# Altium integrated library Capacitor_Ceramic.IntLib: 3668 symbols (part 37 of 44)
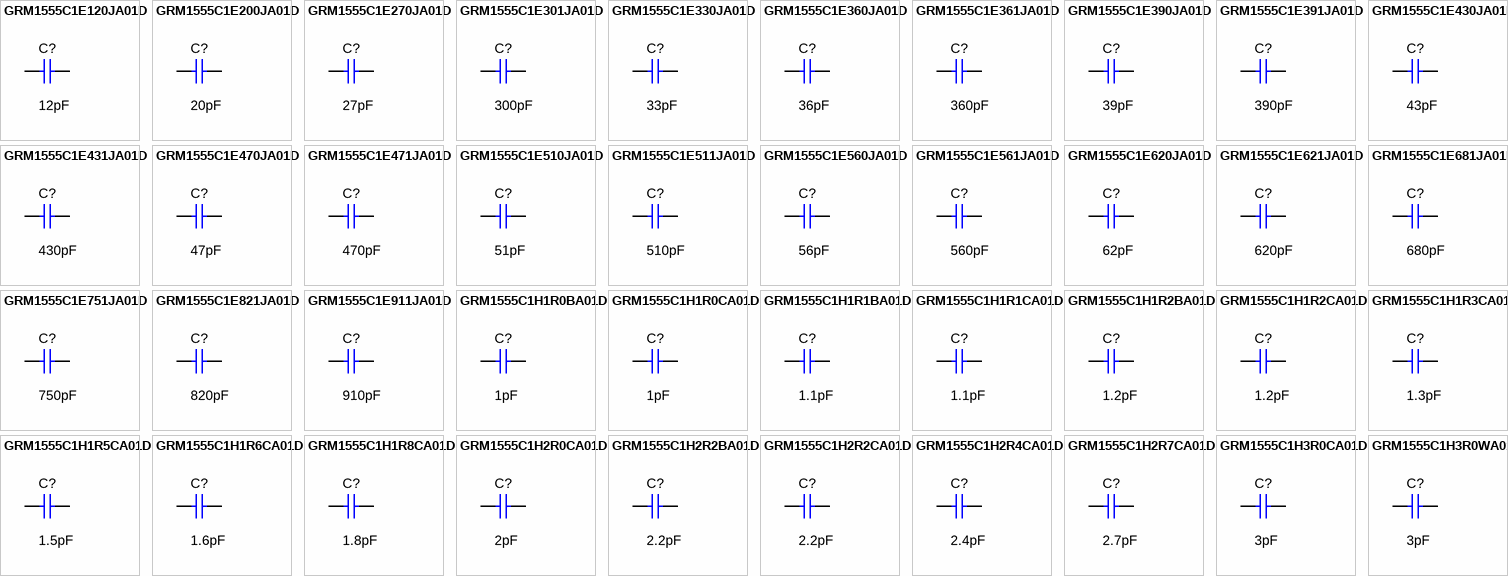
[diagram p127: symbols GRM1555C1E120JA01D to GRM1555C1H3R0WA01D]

## GRM1555C1E911JA01D
designator C?  ValueDisplayed: 910pF  (hidden comment: GRM1555C1E911JA01D)
CAP, CERM, 910 pF, 25 V,+/- 5%, C0G/NP0, 0402; Manufacturer: MuRata; Polarized: N; CompType: Capacitor; Value: 910pF; U/M: EA; Cap_F: 0.00000000091; Tolerance_%: 5; VDC_V: 25; Value2: 25V; TaMin_C: -55; TaMax_C: 125; Cap_Case: 0402; SizeArea_mm2: 0.5; SizeAreaWB_mm2: 3; SizeX_mm: 1; SizeZ_mm: 0.6; AEC Category: Q200
signal-integrity model Cap
simulation model Cap
footprint 0402
footprint 0402M
footprint 0402L
footprint 0402S
pins: 1, 2

## GRM1555C1H1R0BA01D
designator C?  ValueDisplayed: 1pF  (hidden comment: GRM1555C1H1R0BA01D)
CAP, CERM, 1 pF, 50 V,+/- 10%, C0G/NP0, 0402; Manufacturer: MuRata; Polarized: N; CompType: Capacitor; Value: 1pF; U/M: EA; Cap_F: 0.000000000001; Tolerance_%: 10; VDC_V: 50; Value2: 50V; TaMin_C: -55; TaMax_C: 125; Cap_Case: 0402; SizeArea_mm2: 0.5; SizeAreaWB_mm2: 3; SizeX_mm: 1; SizeZ_mm: 0.6; AEC Category: Q200
signal-integrity model Cap
simulation model Cap
footprint 0402
footprint 0402M
footprint 0402L
footprint 0402S
pins: 1, 2

## GRM1555C1H1R0CA01D
designator C?  ValueDisplayed: 1pF  (hidden comment: GRM1555C1H1R0CA01D)
CAP, CERM, 1 pF, 50 V,+/- 5%, C0G/NP0, 0402; Manufacturer: MuRata; Polarized: N; CompType: Capacitor; Value: 1pF; U/M: EA; Cap_F: 0.000000000001; Tolerance_%: 5; VDC_V: 50; Value2: 50V; TaMin_C: -55; TaMax_C: 125; Cap_Case: 0402; SizeArea_mm2: 0.5; SizeAreaWB_mm2: 3; SizeX_mm: 1; SizeZ_mm: 0.6; AEC Category: Q200; Green_Lifecycle: Active; Green_REACh: Passed
signal-integrity model Cap
simulation model Cap
footprint 0402
footprint 0402M
footprint 0402L
footprint 0402S
pins: 1, 2

## GRM1555C1H1R1BA01D
designator C?  ValueDisplayed: 1.1pF  (hidden comment: GRM1555C1H1R1BA01D)
CAP, CERM, 1.1 pF, 50 V,+/- 10%, C0G/NP0, 0402; Manufacturer: MuRata; Polarized: N; CompType: Capacitor; Value: 1.1pF; U/M: EA; Cap_F: 0.0000000000011; Tolerance_%: 10; VDC_V: 50; Value2: 50V; TaMin_C: -55; TaMax_C: 125; Cap_Case: 0402; SizeArea_mm2: 0.5; SizeAreaWB_mm2: 3; SizeX_mm: 1; SizeZ_mm: 0.6; AEC Category: Q200
signal-integrity model Cap
simulation model Cap
footprint 0402
footprint 0402M
footprint 0402L
footprint 0402S
pins: 1, 2

## GRM1555C1H1R1CA01D
designator C?  ValueDisplayed: 1.1pF  (hidden comment: GRM1555C1H1R1CA01D)
CAP, CERM, 1.1 pF, 50 V,+/- 5%, C0G/NP0, 0402; Manufacturer: MuRata; Polarized: N; CompType: Capacitor; Value: 1.1pF; U/M: EA; Cap_F: 0.0000000000011; Tolerance_%: 5; VDC_V: 50; Value2: 50V; TaMin_C: -55; TaMax_C: 125; Cap_Case: 0402; SizeArea_mm2: 0.5; SizeAreaWB_mm2: 3; SizeX_mm: 1; SizeZ_mm: 0.6; AEC Category: Q200
signal-integrity model Cap
simulation model Cap
footprint 0402
footprint 0402M
footprint 0402L
footprint 0402S
pins: 1, 2

## GRM1555C1H1R2BA01D
designator C?  ValueDisplayed: 1.2pF  (hidden comment: GRM1555C1H1R2BA01D)
CAP, CERM, 1.2 pF, 50 V,+/- 8.3%, C0G/NP0, 0402; Manufacturer: MuRata; Polarized: N; CompType: Capacitor; Value: 1.2pF; U/M: EA; Cap_F: 0.0000000000012; Tolerance_%: 8.3; VDC_V: 50; Value2: 50V; TaMin_C: -55; TaMax_C: 125; Cap_Case: 0402; SizeArea_mm2: 0.5; SizeAreaWB_mm2: 3; SizeX_mm: 1; SizeZ_mm: 0.6; AEC Category: Q200
signal-integrity model Cap
simulation model Cap
footprint 0402
footprint 0402M
footprint 0402L
footprint 0402S
pins: 1, 2

## GRM1555C1H1R2CA01D
designator C?  ValueDisplayed: 1.2pF  (hidden comment: GRM1555C1H1R2CA01D)
CAP, CERM, 1.2 pF, 50 V,+/- 5%, C0G/NP0, 0402; Manufacturer: MuRata; Polarized: N; CompType: Capacitor; Value: 1.2pF; U/M: EA; Cap_F: 0.0000000000012; Tolerance_%: 5; VDC_V: 50; Value2: 50V; TaMin_C: -55; TaMax_C: 125; Cap_Case: 0402; SizeArea_mm2: 0.5; SizeAreaWB_mm2: 3; SizeX_mm: 1; SizeZ_mm: 0.6; AEC Category: Q200
signal-integrity model Cap
simulation model Cap
footprint 0402
footprint 0402M
footprint 0402L
footprint 0402S
pins: 1, 2

## GRM1555C1H1R3CA01D
designator C?  ValueDisplayed: 1.3pF  (hidden comment: GRM1555C1H1R3CA01D)
CAP, CERM, 1.3 pF, 50 V,+/- 5%, C0G/NP0, 0402; Manufacturer: MuRata; Polarized: N; CompType: Capacitor; Value: 1.3pF; U/M: EA; Cap_F: 0.0000000000013; Tolerance_%: 5; VDC_V: 50; Value2: 50V; TaMin_C: -55; TaMax_C: 125; Cap_Case: 0402; SizeArea_mm2: 0.5; SizeAreaWB_mm2: 3; SizeX_mm: 1; SizeZ_mm: 0.6; AEC Category: Q200
signal-integrity model Cap
simulation model Cap
footprint 0402
footprint 0402M
footprint 0402L
footprint 0402S
pins: 1, 2

## GRM1555C1H1R5CA01D
designator C?  ValueDisplayed: 1.5pF  (hidden comment: GRM1555C1H1R5CA01D)
CAP, CERM, 1.5 pF, 50 V,+/- 5%, C0G/NP0, 0402; Manufacturer: MuRata; Polarized: N; CompType: Capacitor; Value: 1.5pF; U/M: EA; Cap_F: 0.0000000000015; Tolerance_%: 5; VDC_V: 50; Value2: 50V; TaMin_C: -55; TaMax_C: 125; Cap_Case: 0402; SizeArea_mm2: 0.5; SizeAreaWB_mm2: 3; SizeX_mm: 1; SizeZ_mm: 0.6; AEC Category: Q200; Green_Lifecycle: Active; Green_REACh: Passed
signal-integrity model Cap
simulation model Cap
footprint 0402
footprint 0402M
footprint 0402L
footprint 0402S
pins: 1, 2

## GRM1555C1H1R6CA01D
designator C?  ValueDisplayed: 1.6pF  (hidden comment: GRM1555C1H1R6CA01D)
CAP, CERM, 1.6 pF, 50 V,+/- 5%, C0G/NP0, 0402; Manufacturer: MuRata; Polarized: N; CompType: Capacitor; Value: 1.6pF; U/M: EA; Cap_F: 0.0000000000016; Tolerance_%: 5; VDC_V: 50; Value2: 50V; TaMin_C: -55; TaMax_C: 125; Cap_Case: 0402; SizeArea_mm2: 0.5; SizeAreaWB_mm2: 3; SizeX_mm: 1; SizeZ_mm: 0.6; AEC Category: Q200
signal-integrity model Cap
simulation model Cap
footprint 0402
footprint 0402M
footprint 0402L
footprint 0402S
pins: 1, 2

## GRM1555C1H1R8CA01D
designator C?  ValueDisplayed: 1.8pF  (hidden comment: GRM1555C1H1R8CA01D)
CAP, CERM, 1.8 pF, 50 V,+/- 5%, C0G/NP0, 0402; Manufacturer: MuRata; Polarized: N; CompType: Capacitor; Value: 1.8pF; U/M: EA; Cap_F: 0.0000000000018; Tolerance_%: 5; VDC_V: 50; Value2: 50V; TaMin_C: -55; TaMax_C: 125; Cap_Case: 0402; SizeArea_mm2: 0.5; SizeAreaWB_mm2: 3; SizeX_mm: 1; SizeZ_mm: 0.6; AEC Category: Q200; Green_Lifecycle: Active; Green_REACh: Passed
signal-integrity model Cap
simulation model Cap
footprint 0402
footprint 0402M
footprint 0402L
footprint 0402S
pins: 1, 2

## GRM1555C1H2R0CA01D
designator C?  ValueDisplayed: 2pF  (hidden comment: GRM1555C1H2R0CA01D)
CAP, CERM, 2 pF, 50 V,+/- 5%, C0G/NP0, 0402; Manufacturer: MuRata; Polarized: N; CompType: Capacitor; Value: 2pF; U/M: EA; Cap_F: 0.000000000002; Tolerance_%: 5; VDC_V: 50; Value2: 50V; TaMin_C: -55; TaMax_C: 125; Cap_Case: 0402; SizeArea_mm2: 0.5; SizeAreaWB_mm2: 3; SizeX_mm: 1; SizeZ_mm: 0.6; AEC Category: Q200
signal-integrity model Cap
simulation model Cap
footprint 0402
footprint 0402M
footprint 0402L
footprint 0402S
pins: 1, 2

## GRM1555C1H2R2BA01D
designator C?  ValueDisplayed: 2.2pF  (hidden comment: GRM1555C1H2R2BA01D)
CAP, CERM, 2.2 pF, 50 V,+/- 5%, C0G/NP0, 0402; Manufacturer: MuRata; Polarized: N; CompType: Capacitor; Value: 2.2pF; U/M: EA; Cap_F: 0.0000000000022; Tolerance_%: 5; VDC_V: 50; Value2: 50V; TaMin_C: -55; TaMax_C: 125; Cap_Case: 0402; SizeArea_mm2: 0.5; SizeAreaWB_mm2: 3; SizeX_mm: 1; SizeZ_mm: 0.6; AEC Category: Q200
signal-integrity model Cap
simulation model Cap
footprint 0402
footprint 0402M
footprint 0402L
footprint 0402S
pins: 1, 2

## GRM1555C1H2R2CA01D
designator C?  ValueDisplayed: 2.2pF  (hidden comment: GRM1555C1H2R2CA01D)
CAP, CERM, 2.2 pF, 50 V,+/- 5%, C0G/NP0, 0402; Manufacturer: MuRata; Polarized: N; CompType: Capacitor; Value: 2.2pF; U/M: EA; Cap_F: 0.0000000000022; Tolerance_%: 5; VDC_V: 50; Value2: 50V; TaMin_C: -55; TaMax_C: 125; Cap_Case: 0402; SizeArea_mm2: 0.5; SizeAreaWB_mm2: 3; SizeX_mm: 1; SizeZ_mm: 0.6; AEC Category: Q200
signal-integrity model Cap
simulation model Cap
footprint 0402
footprint 0402M
footprint 0402L
footprint 0402S
pins: 1, 2

## GRM1555C1H2R4CA01D
designator C?  ValueDisplayed: 2.4pF  (hidden comment: GRM1555C1H2R4CA01D)
CAP, CERM, 2.4 pF, 50 V,+/- 5%, C0G/NP0, 0402; Manufacturer: MuRata; Polarized: N; CompType: Capacitor; Value: 2.4pF; U/M: EA; Cap_F: 0.0000000000024; Tolerance_%: 5; VDC_V: 50; Value2: 50V; TaMin_C: -55; TaMax_C: 125; Cap_Case: 0402; SizeArea_mm2: 0.5; SizeAreaWB_mm2: 3; SizeX_mm: 1; SizeZ_mm: 0.6; AEC Category: Q200
signal-integrity model Cap
simulation model Cap
footprint 0402
footprint 0402M
footprint 0402L
footprint 0402S
pins: 1, 2

## GRM1555C1H2R7CA01D
designator C?  ValueDisplayed: 2.7pF  (hidden comment: GRM1555C1H2R7CA01D)
CAP, CERM, 2.7 pF, 50 V,+/- 5%, C0G/NP0, 0402; Manufacturer: MuRata; Polarized: N; CompType: Capacitor; Value: 2.7pF; U/M: EA; Cap_F: 0.0000000000027; Tolerance_%: 5; VDC_V: 50; Value2: 50V; TaMin_C: -55; TaMax_C: 125; Cap_Case: 0402; SizeArea_mm2: 0.5; SizeAreaWB_mm2: 3; SizeX_mm: 1; SizeZ_mm: 0.6; AEC Category: Q200; Green_Lifecycle: Active; Green_REACh: Passed
signal-integrity model Cap
simulation model Cap
footprint 0402
footprint 0402M
footprint 0402L
footprint 0402S
pins: 1, 2

## GRM1555C1H3R0CA01D
designator C?  ValueDisplayed: 3pF  (hidden comment: GRM1555C1H3R0CA01D)
CAP, CERM, 3 pF, 50 V,+/- 5%, C0G/NP0, 0402; Manufacturer: MuRata; Polarized: N; CompType: Capacitor; Value: 3pF; U/M: EA; Cap_F: 0.000000000003; Tolerance_%: 5; VDC_V: 50; Value2: 50V; TaMin_C: -55; TaMax_C: 125; Cap_Case: 0402; SizeArea_mm2: 0.5; SizeAreaWB_mm2: 3; SizeX_mm: 1; SizeZ_mm: 0.6; AEC Category: Q200
signal-integrity model Cap
simulation model Cap
footprint 0402
footprint 0402M
footprint 0402L
footprint 0402S
pins: 1, 2

## GRM1555C1H3R0WA01D
designator C?  ValueDisplayed: 3pF  (hidden comment: GRM1555C1H3R0WA01D)
CAP, CERM, 3 pF, 50 V,+/- 2%, C0G/NP0, 0402; Manufacturer: MuRata; Polarized: N; CompType: Capacitor; Value: 3pF; U/M: EA; Cap_F: 0.000000000003; Tolerance_%: 2; VDC_V: 50; Value2: 50V; TaMin_C: -55; TaMax_C: 125; Cap_Case: 0402; SizeArea_mm2: 0.5; SizeAreaWB_mm2: 3; SizeX_mm: 1; SizeZ_mm: 0.6; AEC Category: Q200
signal-integrity model Cap
simulation model Cap
footprint 0402
footprint 0402M
footprint 0402L
footprint 0402S
pins: 1, 2

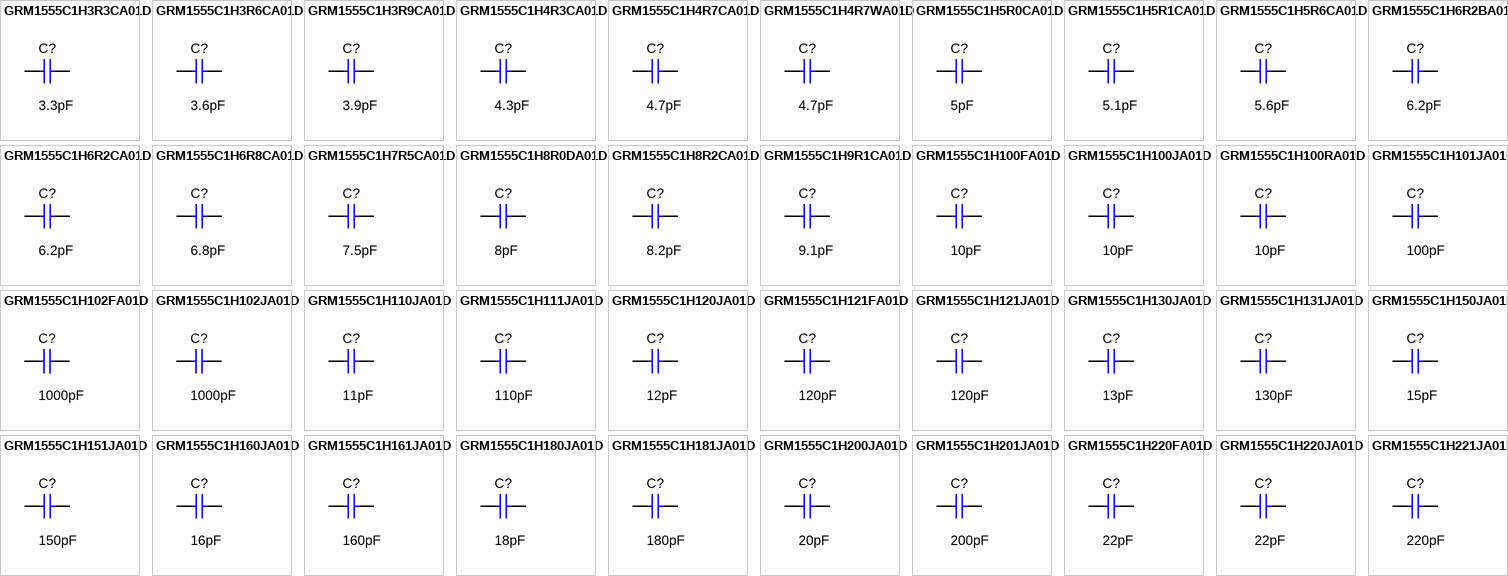
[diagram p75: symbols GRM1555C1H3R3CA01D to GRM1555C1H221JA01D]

## GRM1555C1H3R3CA01D
designator C?  ValueDisplayed: 3.3pF  (hidden comment: GRM1555C1H3R3CA01D)
CAP, CERM, 3.3 pF, 50 V,+/- 5%, C0G/NP0, 0402; Manufacturer: MuRata; Polarized: N; CompType: Capacitor; Value: 3.3pF; U/M: EA; Cap_F: 0.0000000000033; Tolerance_%: 5; VDC_V: 50; Value2: 50V; TaMin_C: -55; TaMax_C: 125; Cap_Case: 0402; SizeArea_mm2: 0.5; SizeAreaWB_mm2: 3; SizeX_mm: 1; SizeZ_mm: 0.6; AEC Category: Q200; Green_Lifecycle: Active; Green_REACh: Passed
signal-integrity model Cap
simulation model Cap
footprint 0402
footprint 0402M
footprint 0402L
footprint 0402S
pins: 1, 2

## GRM1555C1H3R6CA01D
designator C?  ValueDisplayed: 3.6pF  (hidden comment: GRM1555C1H3R6CA01D)
CAP, CERM, 3.6 pF, 50 V,+/- 5%, C0G/NP0, 0402; Manufacturer: MuRata; Polarized: N; CompType: Capacitor; Value: 3.6pF; U/M: EA; Cap_F: 0.0000000000036; Tolerance_%: 5; VDC_V: 50; Value2: 50V; TaMin_C: -55; TaMax_C: 125; Cap_Case: 0402; SizeArea_mm2: 0.5; SizeAreaWB_mm2: 3; SizeX_mm: 1; SizeZ_mm: 0.6; AEC Category: Q200; Green_Lifecycle: Active; Green_REACh: Passed
signal-integrity model Cap
simulation model Cap
footprint 0402
footprint 0402M
footprint 0402L
footprint 0402S
pins: 1, 2

## GRM1555C1H3R9CA01D
designator C?  ValueDisplayed: 3.9pF  (hidden comment: GRM1555C1H3R9CA01D)
CAP, CERM, 3.9 pF, 50 V,+/- 5%, C0G/NP0, 0402; Manufacturer: MuRata; Polarized: N; CompType: Capacitor; Value: 3.9pF; U/M: EA; Cap_F: 0.0000000000039; Tolerance_%: 5; VDC_V: 50; Value2: 50V; TaMin_C: -55; TaMax_C: 125; Cap_Case: 0402; SizeArea_mm2: 0.5; SizeAreaWB_mm2: 3; SizeX_mm: 1; SizeZ_mm: 0.6; AEC Category: Q200
signal-integrity model Cap
simulation model Cap
footprint 0402
footprint 0402M
footprint 0402L
footprint 0402S
pins: 1, 2

## GRM1555C1H4R3CA01D
designator C?  ValueDisplayed: 4.3pF  (hidden comment: GRM1555C1H4R3CA01D)
CAP, CERM, 4.3 pF, 50 V,+/- 5%, C0G/NP0, 0402; Manufacturer: MuRata; Polarized: N; CompType: Capacitor; Value: 4.3pF; U/M: EA; Cap_F: 0.0000000000043; Tolerance_%: 5; VDC_V: 50; Value2: 50V; TaMin_C: -55; TaMax_C: 125; Cap_Case: 0402; SizeArea_mm2: 0.5; SizeAreaWB_mm2: 3; SizeX_mm: 1; SizeZ_mm: 0.6; AEC Category: Q200
signal-integrity model Cap
simulation model Cap
footprint 0402
footprint 0402M
footprint 0402L
footprint 0402S
pins: 1, 2

## GRM1555C1H4R7CA01D
designator C?  ValueDisplayed: 4.7pF  (hidden comment: GRM1555C1H4R7CA01D)
CAP, CERM, 4.7 pF, 50 V,+/- 5%, C0G/NP0, 0402; Manufacturer: MuRata; Polarized: N; CompType: Capacitor; Value: 4.7pF; U/M: EA; Cap_F: 0.0000000000047; Tolerance_%: 5; VDC_V: 50; Value2: 50V; TaMin_C: -55; TaMax_C: 125; Cap_Case: 0402; SizeArea_mm2: 0.5; SizeAreaWB_mm2: 3; SizeX_mm: 1; SizeZ_mm: 0.6; AEC Category: Q200; Green_Lifecycle: Active; Green_REACh: Passed
signal-integrity model Cap
simulation model Cap
footprint 0402
footprint 0402M
footprint 0402L
footprint 0402S
pins: 1, 2

## GRM1555C1H4R7WA01D
designator C?  ValueDisplayed: 4.7pF  (hidden comment: GRM1555C1H4R7WA01D)
CAP, CERM, 4.7 pF, 50 V,+/- 1%, C0G/NP0, 0402; Manufacturer: MuRata; Polarized: N; CompType: Capacitor; Value: 4.7pF; U/M: EA; Cap_F: 0.0000000000047; Tolerance_%: 1; VDC_V: 50; Value2: 50V; TaMin_C: -55; TaMax_C: 125; Cap_Case: 0402; SizeArea_mm2: 0.5; SizeAreaWB_mm2: 3; SizeZ_mm: 0.6; AEC Category: Q200
signal-integrity model Cap
simulation model Cap
footprint 0402
footprint 0402M
footprint 0402L
footprint 0402S
pins: 1, 2

## GRM1555C1H5R0CA01D
designator C?  ValueDisplayed: 5pF  (hidden comment: GRM1555C1H5R0CA01D)
CAP, CERM, 5 pF, 50 V,+/- 5%, C0G/NP0, 0402; Manufacturer: MuRata; Polarized: N; CompType: Capacitor; Value: 5pF; U/M: EA; Cap_F: 0.000000000005; Tolerance_%: 5; VDC_V: 50; Value2: 50V; TaMin_C: -55; TaMax_C: 125; Cap_Case: 0402; SizeArea_mm2: 0.5; SizeAreaWB_mm2: 3; SizeX_mm: 1; SizeZ_mm: 0.6; AEC Category: Q200
signal-integrity model Cap
simulation model Cap
footprint 0402
footprint 0402M
footprint 0402L
footprint 0402S
pins: 1, 2

## GRM1555C1H5R1CA01D
designator C?  ValueDisplayed: 5.1pF  (hidden comment: GRM1555C1H5R1CA01D)
CAP, CERM, 5.1 pF, 50 V,+/- 5%, C0G/NP0, 0402; Manufacturer: MuRata; Polarized: N; CompType: Capacitor; Value: 5.1pF; U/M: EA; Cap_F: 0.0000000000051; Tolerance_%: 5; VDC_V: 50; Value2: 50V; TaMin_C: -55; TaMax_C: 125; Cap_Case: 0402; SizeArea_mm2: 0.5; SizeAreaWB_mm2: 3; SizeX_mm: 1; SizeZ_mm: 0.6; AEC Category: Q200
signal-integrity model Cap
simulation model Cap
footprint 0402
footprint 0402M
footprint 0402L
footprint 0402S
pins: 1, 2

## GRM1555C1H5R6CA01D
designator C?  ValueDisplayed: 5.6pF  (hidden comment: GRM1555C1H5R6CA01D)
CAP, CERM, 5.6 pF, 50 V,+/- 5%, C0G/NP0, 0402; Manufacturer: MuRata; Polarized: N; CompType: Capacitor; Value: 5.6pF; U/M: EA; Cap_F: 0.0000000000056; Tolerance_%: 5; VDC_V: 50; Value2: 50V; TaMin_C: -55; TaMax_C: 125; Cap_Case: 0402; SizeArea_mm2: 0.5; SizeAreaWB_mm2: 3; SizeX_mm: 1; SizeZ_mm: 0.6; AEC Category: Q200
signal-integrity model Cap
simulation model Cap
footprint 0402
footprint 0402M
footprint 0402L
footprint 0402S
pins: 1, 2

## GRM1555C1H6R2BA01D
designator C?  ValueDisplayed: 6.2pF  (hidden comment: GRM1555C1H6R2BA01D)
CAP, CERM, 6.2 pF, 50 V,+/- 1.6%, C0G/NP0, 0402; Manufacturer: MuRata; Polarized: N; CompType: Capacitor; Value: 6.2pF; U/M: EA; Cap_F: 0.0000000000062; Tolerance_%: 1.6; VDC_V: 50; Value2: 50V; TaMin_C: -55; TaMax_C: 125; Cap_Case: 0402; SizeArea_mm2: 0.5; SizeAreaWB_mm2: 3; SizeX_mm: 1; SizeZ_mm: 0.6; AEC Category: Q200
signal-integrity model Cap
simulation model Cap
footprint 0402
footprint 0402M
footprint 0402L
footprint 0402S
pins: 1, 2

## GRM1555C1H6R2CA01D
designator C?  ValueDisplayed: 6.2pF  (hidden comment: GRM1555C1H6R2CA01D)
CAP, CERM, 6.2 pF, 50 V,+/- 5%, C0G/NP0, 0402; Manufacturer: MuRata; Polarized: N; CompType: Capacitor; Value: 6.2pF; U/M: EA; Cap_F: 0.0000000000062; Tolerance_%: 5; VDC_V: 50; Value2: 50V; TaMin_C: -55; TaMax_C: 125; Cap_Case: 0402; SizeArea_mm2: 0.5; SizeAreaWB_mm2: 3; SizeX_mm: 1; SizeZ_mm: 0.6; AEC Category: Q200; Green_Lifecycle: Active; Green_REACh: Passed
signal-integrity model Cap
simulation model Cap
footprint 0402
footprint 0402M
footprint 0402L
footprint 0402S
pins: 1, 2

## GRM1555C1H6R8CA01D
designator C?  ValueDisplayed: 6.8pF  (hidden comment: GRM1555C1H6R8CA01D)
CAP, CERM, 6.8 pF, 50 V,+/- 5%, C0G/NP0, 0402; Manufacturer: MuRata; Polarized: N; CompType: Capacitor; Value: 6.8pF; U/M: EA; Cap_F: 0.0000000000068; Tolerance_%: 5; VDC_V: 50; Value2: 50V; TaMin_C: -55; TaMax_C: 125; Cap_Case: 0402; SizeArea_mm2: 0.5; SizeAreaWB_mm2: 3; SizeX_mm: 1; SizeZ_mm: 0.6; AEC Category: Q200; Green_Lifecycle: Active; Green_REACh: Passed
signal-integrity model Cap
simulation model Cap
footprint 0402
footprint 0402M
footprint 0402L
footprint 0402S
pins: 1, 2

## GRM1555C1H7R5CA01D
designator C?  ValueDisplayed: 7.5pF  (hidden comment: GRM1555C1H7R5CA01D)
CAP, CERM, 7.5 pF, 50 V,+/- 5%, C0G/NP0, 0402; Manufacturer: MuRata; Polarized: N; CompType: Capacitor; Value: 7.5pF; U/M: EA; Cap_F: 0.0000000000075; Tolerance_%: 5; VDC_V: 50; Value2: 50V; TaMin_C: -55; TaMax_C: 125; Cap_Case: 0402; SizeArea_mm2: 0.5; SizeAreaWB_mm2: 3; SizeX_mm: 1; SizeZ_mm: 0.6; AEC Category: Q200
signal-integrity model Cap
simulation model Cap
footprint 0402
footprint 0402M
footprint 0402L
footprint 0402S
pins: 1, 2

## GRM1555C1H8R0DA01D
designator C?  ValueDisplayed: 8pF  (hidden comment: GRM1555C1H8R0DA01D)
CAP, CERM, 8 pF, 50 V,+/- 6%, C0G/NP0, 0402; Manufacturer: MuRata; Polarized: N; CompType: Capacitor; Value: 8pF; U/M: EA; Cap_F: 0.000000000008; Tolerance_%: 6; VDC_V: 50; Value2: 50V; TaMin_C: -55; TaMax_C: 125; Cap_Case: 0402; SizeArea_mm2: 0.5; SizeAreaWB_mm2: 3; SizeX_mm: 1; SizeZ_mm: 0.6; AEC Category: Q200
signal-integrity model Cap
simulation model Cap
footprint 0402
footprint 0402M
footprint 0402L
footprint 0402S
pins: 1, 2

## GRM1555C1H8R2CA01D
designator C?  ValueDisplayed: 8.2pF  (hidden comment: GRM1555C1H8R2CA01D)
CAP, CERM, 8.2 pF, 50 V,+/- 5%, C0G/NP0, 0402; Manufacturer: MuRata; Polarized: N; CompType: Capacitor; Value: 8.2pF; U/M: EA; Cap_F: 0.0000000000082; Tolerance_%: 5; VDC_V: 50; Value2: 50V; TaMin_C: -55; TaMax_C: 125; Cap_Case: 0402; SizeArea_mm2: 0.5; SizeAreaWB_mm2: 3; SizeX_mm: 1; SizeZ_mm: 0.6; AEC Category: Q200
signal-integrity model Cap
simulation model Cap
footprint 0402
footprint 0402M
footprint 0402L
footprint 0402S
pins: 1, 2

## GRM1555C1H9R1CA01D
designator C?  ValueDisplayed: 9.1pF  (hidden comment: GRM1555C1H9R1CA01D)
CAP, CERM, 9.1 pF, 50 V,+/- 5%, C0G/NP0, 0402; Manufacturer: MuRata; Polarized: N; CompType: Capacitor; Value: 9.1pF; U/M: EA; Cap_F: 0.0000000000091; Tolerance_%: 5; VDC_V: 50; Value2: 50V; TaMin_C: -55; TaMax_C: 125; Cap_Case: 0402; SizeArea_mm2: 0.5; SizeAreaWB_mm2: 3; SizeX_mm: 1; SizeZ_mm: 0.6; AEC Category: Q200
signal-integrity model Cap
simulation model Cap
footprint 0402
footprint 0402M
footprint 0402L
footprint 0402S
pins: 1, 2

## GRM1555C1H100FA01D
designator C?  ValueDisplayed: 10pF  (hidden comment: GRM1555C1H100FA01D)
CAP, CERM, 10 pF, 50 V,+/- 1%, C0G/NP0, 0402; Manufacturer: MuRata; Polarized: N; CompType: Capacitor; Value: 10pF; U/M: EA; Cap_F: 0.00000000001; Tolerance_%: 1; VDC_V: 50; Value2: 50V; TaMin_C: -55; TaMax_C: 125; Cap_Case: 0402; SizeArea_mm2: 0.5; SizeAreaWB_mm2: 3; SizeZ_mm: 0.6; AEC Category: Q200
signal-integrity model Cap
simulation model Cap
footprint 0402
footprint 0402M
footprint 0402L
footprint 0402S
pins: 1, 2

## GRM1555C1H100JA01D
designator C?  ValueDisplayed: 10pF  (hidden comment: GRM1555C1H100JA01D)
CAP, CERM, 10 pF, 50 V,+/- 5%, C0G/NP0, 0402; Manufacturer: MuRata; Polarized: N; CompType: Capacitor; Value: 10pF; U/M: EA; Cap_F: 0.00000000001; Tolerance_%: 5; VDC_V: 50; Value2: 50V; TaMin_C: -55; TaMax_C: 125; Cap_Case: 0402; SizeArea_mm2: 0.5; SizeAreaWB_mm2: 3; SizeX_mm: 1; SizeZ_mm: 0.6; AEC Category: Q200; Green_Lifecycle: Active; Green_REACh: Passed
signal-integrity model Cap
simulation model Cap
footprint 0402
footprint 0402M
footprint 0402L
footprint 0402S
pins: 1, 2

## GRM1555C1H100RA01D
designator C?  ValueDisplayed: 10pF  (hidden comment: GRM1555C1H100RA01D)
CAP, CERM, 10 pF, 50 V,+/- 4%, C0G/NP0, 0402; Manufacturer: MuRata; Polarized: N; CompType: Capacitor; Value: 10pF; U/M: EA; Cap_F: 0.00000000001; Tolerance_%: 4; VDC_V: 50; Value2: 50V; TaMin_C: -55; TaMax_C: 125; Cap_Case: 0402; SizeArea_mm2: 0.5; SizeAreaWB_mm2: 3; SizeX_mm: 1; SizeZ_mm: 0.6; AEC Category: Q200
signal-integrity model Cap
simulation model Cap
footprint 0402
footprint 0402M
footprint 0402L
footprint 0402S
pins: 1, 2

## GRM1555C1H101JA01D
designator C?  ValueDisplayed: 100pF  (hidden comment: GRM1555C1H101JA01D)
CAP, CERM, 100 pF, 50 V,+/- 5%, C0G/NP0, 0402; Manufacturer: MuRata; Polarized: N; CompType: Capacitor; Value: 100pF; U/M: EA; Cap_F: 0.0000000001; Tolerance_%: 5; VDC_V: 50; Value2: 50V; TaMin_C: -55; TaMax_C: 125; Cap_Case: 0402; SizeArea_mm2: 0.5; SizeAreaWB_mm2: 3; SizeX_mm: 1; SizeZ_mm: 0.6; AEC Category: Q200; Green_Lifecycle: Active; Green_REACh: Passed
signal-integrity model Cap
simulation model Cap
footprint 0402
footprint 0402M
footprint 0402L
footprint 0402S
pins: 1, 2

## GRM1555C1H102FA01D
designator C?  ValueDisplayed: 1000pF  (hidden comment: GRM1555C1H102FA01D)
CAP, CERM, 1000 pF, 50 V,+/- 1%, C0G/NP0, 0402; Manufacturer: MuRata; Polarized: N; CompType: Capacitor; Value: 1000pF; U/M: EA; Cap_F: 0.000000001; Tolerance_%: 1; VDC_V: 50; Value2: 50V; TaMin_C: -55; TaMax_C: 125; Cap_Case: 0402; SizeArea_mm2: 0.5; SizeAreaWB_mm2: 3; SizeZ_mm: 0.6; AEC Category: Q200
signal-integrity model Cap
simulation model Cap
footprint 0402
footprint 0402M
footprint 0402L
footprint 0402S
pins: 1, 2

## GRM1555C1H102JA01D
designator C?  ValueDisplayed: 1000pF  (hidden comment: GRM1555C1H102JA01D)
CAP, CERM, 1000 pF, 50 V,+/- 5%, C0G/NP0, 0402; Manufacturer: MuRata; Polarized: N; CompType: Capacitor; Value: 1000pF; U/M: EA; Cap_F: 0.000000001; Tolerance_%: 5; VDC_V: 50; Value2: 50V; TaMin_C: -55; TaMax_C: 125; Cap_Case: 0402; SizeArea_mm2: 0.5; SizeAreaWB_mm2: 3; SizeX_mm: 1; SizeZ_mm: 0.6; AEC Category: Q200; Green_Lifecycle: Active; Green_REACh: Passed
signal-integrity model Cap
simulation model Cap
footprint 0402
footprint 0402M
footprint 0402L
footprint 0402S
pins: 1, 2

## GRM1555C1H110JA01D
designator C?  ValueDisplayed: 11pF  (hidden comment: GRM1555C1H110JA01D)
CAP, CERM, 11 pF, 50 V,+/- 5%, C0G/NP0, 0402; Manufacturer: MuRata; Polarized: N; CompType: Capacitor; Value: 11pF; U/M: EA; Cap_F: 0.000000000011; Tolerance_%: 5; VDC_V: 50; Value2: 50V; TaMin_C: -55; TaMax_C: 125; Cap_Case: 0402; SizeArea_mm2: 0.5; SizeAreaWB_mm2: 3; SizeX_mm: 1; SizeZ_mm: 0.6; AEC Category: Q200
signal-integrity model Cap
simulation model Cap
footprint 0402
footprint 0402M
footprint 0402L
footprint 0402S
pins: 1, 2

## GRM1555C1H111JA01D
designator C?  ValueDisplayed: 110pF  (hidden comment: GRM1555C1H111JA01D)
CAP, CERM, 110 pF, 50 V,+/- 5%, C0G/NP0, 0402; Manufacturer: MuRata; Polarized: N; CompType: Capacitor; Value: 110pF; U/M: EA; Cap_F: 0.00000000011; Tolerance_%: 5; VDC_V: 50; Value2: 50V; TaMin_C: -55; TaMax_C: 125; Cap_Case: 0402; SizeArea_mm2: 0.5; SizeAreaWB_mm2: 3; SizeX_mm: 1; SizeZ_mm: 0.6; AEC Category: Q200
signal-integrity model Cap
simulation model Cap
footprint 0402
footprint 0402M
footprint 0402L
footprint 0402S
pins: 1, 2

## GRM1555C1H120JA01D
designator C?  ValueDisplayed: 12pF  (hidden comment: GRM1555C1H120JA01D)
CAP, CERM, 12 pF, 50 V,+/- 5%, C0G/NP0, 0402; Manufacturer: MuRata; Polarized: N; CompType: Capacitor; Value: 12pF; U/M: EA; Cap_F: 0.000000000012; Tolerance_%: 5; VDC_V: 50; Value2: 50V; TaMin_C: -55; TaMax_C: 125; Cap_Case: 0402; SizeArea_mm2: 0.5; SizeAreaWB_mm2: 3; SizeX_mm: 1; SizeZ_mm: 0.6; AEC Category: Q200; Green_Lifecycle: Active; Green_REACh: Passed
signal-integrity model Cap
simulation model Cap
footprint 0402
footprint 0402M
footprint 0402L
footprint 0402S
pins: 1, 2

## GRM1555C1H121FA01D
designator C?  ValueDisplayed: 120pF  (hidden comment: GRM1555C1H121FA01D)
CAP, CERM, 120 pF, 50 V,+/- 1%, C0G/NP0, 0402; Manufacturer: MuRata; Polarized: N; CompType: Capacitor; Value: 120pF; U/M: EA; Cap_F: 0.00000000012; Tolerance_%: 1; VDC_V: 50; Value2: 50V; TaMin_C: -55; TaMax_C: 125; Cap_Case: 0402; SizeArea_mm2: 0.5; SizeAreaWB_mm2: 3; SizeZ_mm: 0.6; AEC Category: Q200
signal-integrity model Cap
simulation model Cap
footprint 0402
footprint 0402M
footprint 0402L
footprint 0402S
pins: 1, 2

## GRM1555C1H121JA01D
designator C?  ValueDisplayed: 120pF  (hidden comment: GRM1555C1H121JA01D)
CAP, CERM, 120 pF, 50 V,+/- 5%, C0G/NP0, 0402; Manufacturer: MuRata; Polarized: N; CompType: Capacitor; Value: 120pF; U/M: EA; Cap_F: 0.00000000012; Tolerance_%: 5; VDC_V: 50; Value2: 50V; TaMin_C: -55; TaMax_C: 125; Cap_Case: 0402; SizeArea_mm2: 0.5; SizeAreaWB_mm2: 3; SizeX_mm: 1; SizeZ_mm: 0.6; AEC Category: Q200
signal-integrity model Cap
simulation model Cap
footprint 0402
footprint 0402M
footprint 0402L
footprint 0402S
pins: 1, 2

## GRM1555C1H130JA01D
designator C?  ValueDisplayed: 13pF  (hidden comment: GRM1555C1H130JA01D)
CAP, CERM, 13 pF, 50 V,+/- 5%, C0G/NP0, 0402; Manufacturer: MuRata; Polarized: N; CompType: Capacitor; Value: 13pF; U/M: EA; Cap_F: 0.000000000013; Tolerance_%: 5; VDC_V: 50; Value2: 50V; TaMin_C: -55; TaMax_C: 125; Cap_Case: 0402; SizeArea_mm2: 0.5; SizeAreaWB_mm2: 3; SizeX_mm: 1; SizeZ_mm: 0.6; AEC Category: Q200
signal-integrity model Cap
simulation model Cap
footprint 0402
footprint 0402M
footprint 0402L
footprint 0402S
pins: 1, 2

## GRM1555C1H131JA01D
designator C?  ValueDisplayed: 130pF  (hidden comment: GRM1555C1H131JA01D)
CAP, CERM, 130 pF, 50 V,+/- 5%, C0G/NP0, 0402; Manufacturer: MuRata; Polarized: N; CompType: Capacitor; Value: 130pF; U/M: EA; Cap_F: 0.00000000013; Tolerance_%: 5; VDC_V: 50; Value2: 50V; TaMin_C: -55; TaMax_C: 125; Cap_Case: 0402; SizeArea_mm2: 0.5; SizeAreaWB_mm2: 3; SizeX_mm: 1; SizeZ_mm: 0.6; AEC Category: Q200
signal-integrity model Cap
simulation model Cap
footprint 0402
footprint 0402M
footprint 0402L
footprint 0402S
pins: 1, 2

## GRM1555C1H150JA01D
designator C?  ValueDisplayed: 15pF  (hidden comment: GRM1555C1H150JA01D)
CAP, CERM, 15 pF, 50 V,+/- 5%, C0G/NP0, 0402; Manufacturer: MuRata; Polarized: N; CompType: Capacitor; Value: 15pF; U/M: EA; Cap_F: 0.000000000015; Tolerance_%: 5; VDC_V: 50; Value2: 50V; TaMin_C: -55; TaMax_C: 125; Cap_Case: 0402; SizeArea_mm2: 0.5; SizeAreaWB_mm2: 3; SizeX_mm: 1; SizeZ_mm: 0.6; AEC Category: Q200; Green_Lifecycle: Active; Green_REACh: Passed
signal-integrity model Cap
simulation model Cap
footprint 0402
footprint 0402M
footprint 0402L
footprint 0402S
pins: 1, 2

## GRM1555C1H151JA01D
designator C?  ValueDisplayed: 150pF  (hidden comment: GRM1555C1H151JA01D)
CAP, CERM, 150 pF, 50 V,+/- 5%, C0G/NP0, 0402; Manufacturer: MuRata; Polarized: N; CompType: Capacitor; Value: 150pF; U/M: EA; Cap_F: 0.00000000015; Tolerance_%: 5; VDC_V: 50; Value2: 50V; TaMin_C: -55; TaMax_C: 125; Cap_Case: 0402; SizeArea_mm2: 0.5; SizeAreaWB_mm2: 3; SizeX_mm: 1; SizeZ_mm: 0.6; AEC Category: Q200; Green_Lifecycle: Active; Green_REACh: Passed
signal-integrity model Cap
simulation model Cap
footprint 0402
footprint 0402M
footprint 0402L
footprint 0402S
pins: 1, 2

## GRM1555C1H160JA01D
designator C?  ValueDisplayed: 16pF  (hidden comment: GRM1555C1H160JA01D)
CAP, CERM, 16 pF, 50 V,+/- 5%, C0G/NP0, 0402; Manufacturer: MuRata; Polarized: N; CompType: Capacitor; Value: 16pF; U/M: EA; Cap_F: 0.000000000016; Tolerance_%: 5; VDC_V: 50; Value2: 50V; TaMin_C: -55; TaMax_C: 125; Cap_Case: 0402; SizeArea_mm2: 0.5; SizeAreaWB_mm2: 3; SizeX_mm: 1; SizeZ_mm: 0.6; AEC Category: Q200
signal-integrity model Cap
simulation model Cap
footprint 0402
footprint 0402M
footprint 0402L
footprint 0402S
pins: 1, 2

## GRM1555C1H161JA01D
designator C?  ValueDisplayed: 160pF  (hidden comment: GRM1555C1H161JA01D)
CAP, CERM, 160 pF, 50 V,+/- 5%, C0G/NP0, 0402; Manufacturer: MuRata; Polarized: N; CompType: Capacitor; Value: 160pF; U/M: EA; Cap_F: 0.00000000016; Tolerance_%: 5; VDC_V: 50; Value2: 50V; TaMin_C: -55; TaMax_C: 125; Cap_Case: 0402; SizeArea_mm2: 0.5; SizeAreaWB_mm2: 3; SizeX_mm: 1; SizeZ_mm: 0.6; AEC Category: Q200; Green_Lifecycle: Active; Green_REACh: Passed
signal-integrity model Cap
simulation model Cap
footprint 0402
footprint 0402M
footprint 0402L
footprint 0402S
pins: 1, 2

## GRM1555C1H180JA01D
designator C?  ValueDisplayed: 18pF  (hidden comment: GRM1555C1H180JA01D)
CAP, CERM, 18 pF, 50 V,+/- 5%, C0G/NP0, 0402; Manufacturer: MuRata; Polarized: N; CompType: Capacitor; Value: 18pF; U/M: EA; Cap_F: 0.000000000018; Tolerance_%: 5; VDC_V: 50; Value2: 50V; TaMin_C: -55; TaMax_C: 125; Cap_Case: 0402; SizeArea_mm2: 0.5; SizeAreaWB_mm2: 3; SizeX_mm: 1; SizeZ_mm: 0.6; AEC Category: Q200; Green_Lifecycle: Active; Green_REACh: Passed
signal-integrity model Cap
simulation model Cap
footprint 0402
footprint 0402M
footprint 0402L
footprint 0402S
pins: 1, 2

## GRM1555C1H181JA01D
designator C?  ValueDisplayed: 180pF  (hidden comment: GRM1555C1H181JA01D)
CAP, CERM, 180 pF, 50 V,+/- 5%, C0G/NP0, 0402; Manufacturer: MuRata; Polarized: N; CompType: Capacitor; Value: 180pF; U/M: EA; Cap_F: 0.00000000018; Tolerance_%: 5; VDC_V: 50; Value2: 50V; TaMin_C: -55; TaMax_C: 125; Cap_Case: 0402; SizeArea_mm2: 0.5; SizeAreaWB_mm2: 3; SizeX_mm: 1; SizeZ_mm: 0.6; AEC Category: Q200; Green_Lifecycle: Active; Green_REACh: Passed
signal-integrity model Cap
simulation model Cap
footprint 0402
footprint 0402M
footprint 0402L
footprint 0402S
pins: 1, 2

## GRM1555C1H200JA01D
designator C?  ValueDisplayed: 20pF  (hidden comment: GRM1555C1H200JA01D)
CAP, CERM, 20 pF, 50 V,+/- 5%, C0G/NP0, 0402; Manufacturer: MuRata; Polarized: N; CompType: Capacitor; Value: 20pF; U/M: EA; Cap_F: 0.00000000002; Tolerance_%: 5; VDC_V: 50; Value2: 50V; TaMin_C: -55; TaMax_C: 125; Cap_Case: 0402; SizeArea_mm2: 0.5; SizeAreaWB_mm2: 3; SizeX_mm: 1; SizeZ_mm: 0.6; AEC Category: Q200; Green_Lifecycle: Active; Green_REACh: Passed
signal-integrity model Cap
simulation model Cap
footprint 0402
footprint 0402M
footprint 0402L
footprint 0402S
pins: 1, 2

## GRM1555C1H201JA01D
designator C?  ValueDisplayed: 200pF  (hidden comment: GRM1555C1H201JA01D)
CAP, CERM, 200 pF, 50 V,+/- 5%, C0G/NP0, 0402; Manufacturer: MuRata; Polarized: N; CompType: Capacitor; Value: 200pF; U/M: EA; Cap_F: 0.0000000002; Tolerance_%: 5; VDC_V: 50; Value2: 50V; TaMin_C: -55; TaMax_C: 125; Cap_Case: 0402; SizeArea_mm2: 0.5; SizeAreaWB_mm2: 3; SizeX_mm: 1; SizeZ_mm: 0.6; AEC Category: Q200; Green_Lifecycle: Active; Green_REACh: Passed
signal-integrity model Cap
simulation model Cap
footprint 0402
footprint 0402M
footprint 0402L
footprint 0402S
pins: 1, 2

## GRM1555C1H220FA01D
designator C?  ValueDisplayed: 22pF  (hidden comment: GRM1555C1H220FA01D)
CAP, CERM, 22 pF, 50 V,+/- 1%, C0G/NP0, 0402; Manufacturer: MuRata; Polarized: N; CompType: Capacitor; Value: 22pF; U/M: EA; Cap_F: 0.000000000022; Tolerance_%: 1; VDC_V: 50; Value2: 50V; TaMin_C: -55; TaMax_C: 125; Cap_Case: 0402; SizeArea_mm2: 0.5; SizeAreaWB_mm2: 3; SizeZ_mm: 0.6; AEC Category: Q200; Green_Lifecycle: Active; Green_REACh: Passed
signal-integrity model Cap
simulation model Cap
footprint 0402
footprint 0402M
footprint 0402L
footprint 0402S
pins: 1, 2

## GRM1555C1H220JA01D
designator C?  ValueDisplayed: 22pF  (hidden comment: GRM1555C1H220JA01D)
CAP, CERM, 22 pF, 50 V,+/- 5%, C0G/NP0, 0402; Manufacturer: MuRata; Polarized: N; CompType: Capacitor; Value: 22pF; U/M: EA; Cap_F: 0.000000000022; Tolerance_%: 5; VDC_V: 50; Value2: 50V; TaMin_C: -55; TaMax_C: 125; Cap_Case: 0402; SizeArea_mm2: 0.5; SizeAreaWB_mm2: 3; SizeX_mm: 1; SizeZ_mm: 0.6; AEC Category: Q200; Green_Lifecycle: Active; Green_REACh: Passed
signal-integrity model Cap
simulation model Cap
footprint 0402
footprint 0402M
footprint 0402L
footprint 0402S
pins: 1, 2

## GRM1555C1H221JA01D
designator C?  ValueDisplayed: 220pF  (hidden comment: GRM1555C1H221JA01D)
CAP, CERM, 220 pF, 50 V,+/- 5%, C0G/NP0, 0402; Manufacturer: MuRata; Polarized: N; CompType: Capacitor; Value: 220pF; U/M: EA; Cap_F: 0.00000000022; Tolerance_%: 5; VDC_V: 50; Value2: 50V; TaMin_C: -55; TaMax_C: 125; Cap_Case: 0402; SizeArea_mm2: 0.5; SizeAreaWB_mm2: 3; SizeX_mm: 1; SizeZ_mm: 0.6; AEC Category: Q200; Green_Lifecycle: Active; Green_REACh: Passed
signal-integrity model Cap
simulation model Cap
footprint 0402
footprint 0402M
footprint 0402L
footprint 0402S
pins: 1, 2

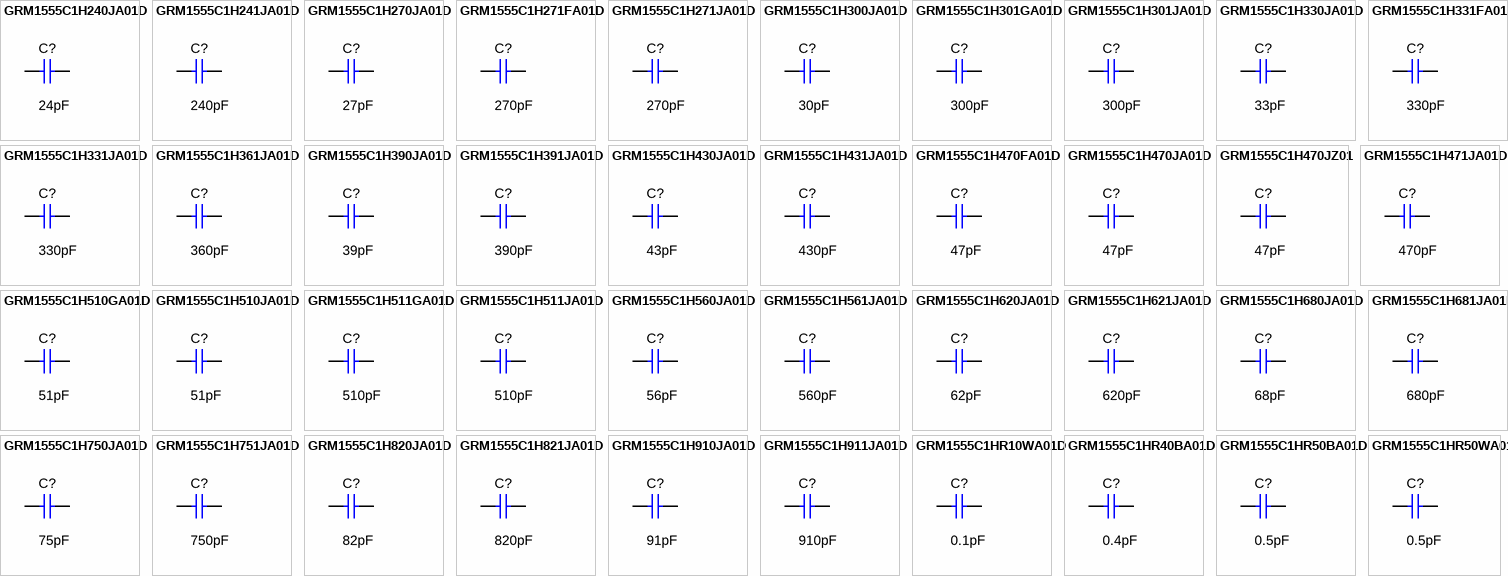
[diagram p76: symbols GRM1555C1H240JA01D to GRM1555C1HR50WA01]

## GRM1555C1H240JA01D
designator C?  ValueDisplayed: 24pF  (hidden comment: GRM1555C1H240JA01D)
CAP, CERM, 24 pF, 50 V,+/- 5%, C0G/NP0, 0402; Manufacturer: MuRata; Polarized: N; CompType: Capacitor; Value: 24pF; U/M: EA; Cap_F: 0.000000000024; Tolerance_%: 5; VDC_V: 50; Value2: 50V; TaMin_C: -55; TaMax_C: 125; Cap_Case: 0402; SizeArea_mm2: 0.5; SizeAreaWB_mm2: 3; SizeX_mm: 1; SizeZ_mm: 0.6; AEC Category: Q200
signal-integrity model Cap
simulation model Cap
footprint 0402
footprint 0402M
footprint 0402L
footprint 0402S
pins: 1, 2

## GRM1555C1H241JA01D
designator C?  ValueDisplayed: 240pF  (hidden comment: GRM1555C1H241JA01D)
CAP, CERM, 240 pF, 50 V,+/- 5%, C0G/NP0, 0402; Manufacturer: MuRata; Polarized: N; CompType: Capacitor; Value: 240pF; U/M: EA; Cap_F: 0.00000000024; Tolerance_%: 5; VDC_V: 50; Value2: 50V; TaMin_C: -55; TaMax_C: 125; Cap_Case: 0402; SizeArea_mm2: 0.5; SizeAreaWB_mm2: 3; SizeX_mm: 1; SizeZ_mm: 0.6; AEC Category: Q200; Green_Lifecycle: Active; Green_REACh: Passed
signal-integrity model Cap
simulation model Cap
footprint 0402
footprint 0402M
footprint 0402L
footprint 0402S
pins: 1, 2

## GRM1555C1H270JA01D
designator C?  ValueDisplayed: 27pF  (hidden comment: GRM1555C1H270JA01D)
CAP, CERM, 27 pF, 50 V,+/- 5%, C0G/NP0, 0402; Manufacturer: MuRata; Polarized: N; CompType: Capacitor; Value: 27pF; U/M: EA; Cap_F: 0.000000000027; Tolerance_%: 5; VDC_V: 50; Value2: 50V; TaMin_C: -55; TaMax_C: 125; Cap_Case: 0402; SizeArea_mm2: 0.5; SizeAreaWB_mm2: 3; SizeX_mm: 1; SizeZ_mm: 0.6; AEC Category: Q200; Green_Lifecycle: Active; Green_REACh: Passed
signal-integrity model Cap
simulation model Cap
footprint 0402
footprint 0402M
footprint 0402L
footprint 0402S
pins: 1, 2

## GRM1555C1H271FA01D
designator C?  ValueDisplayed: 270pF  (hidden comment: GRM1555C1H271FA01D)
CAP, CERM, 270 pF, 50 V,+/- 1%, C0G/NP0, 0402; Manufacturer: MuRata; Polarized: N; CompType: Capacitor; Value: 270pF; U/M: EA; Cap_F: 0.00000000027; Tolerance_%: 1; VDC_V: 50; Value2: 50V; TaMin_C: -55; TaMax_C: 125; Cap_Case: 0402; SizeArea_mm2: 0.5; SizeAreaWB_mm2: 3; SizeZ_mm: 0.6; AEC Category: Q200
signal-integrity model Cap
simulation model Cap
footprint 0402
footprint 0402M
footprint 0402L
footprint 0402S
pins: 1, 2

## GRM1555C1H271JA01D
designator C?  ValueDisplayed: 270pF  (hidden comment: GRM1555C1H271JA01D)
CAP, CERM, 270 pF, 50 V,+/- 5%, C0G/NP0, 0402; Manufacturer: MuRata; Polarized: N; CompType: Capacitor; Value: 270pF; U/M: EA; Cap_F: 0.00000000027; Tolerance_%: 5; VDC_V: 50; Value2: 50V; TaMin_C: -55; TaMax_C: 125; Cap_Case: 0402; SizeArea_mm2: 0.5; SizeAreaWB_mm2: 3; SizeX_mm: 1; SizeZ_mm: 0.6; AEC Category: Q200
signal-integrity model Cap
simulation model Cap
footprint 0402
footprint 0402M
footprint 0402L
footprint 0402S
pins: 1, 2

## GRM1555C1H300JA01D
designator C?  ValueDisplayed: 30pF  (hidden comment: GRM1555C1H300JA01D)
CAP, CERM, 30 pF, 50 V,+/- 5%, C0G/NP0, 0402; Manufacturer: MuRata; Polarized: N; CompType: Capacitor; Value: 30pF; U/M: EA; Cap_F: 0.00000000003; Tolerance_%: 5; VDC_V: 50; Value2: 50V; TaMin_C: -55; TaMax_C: 125; Cap_Case: 0402; SizeArea_mm2: 0.5; SizeAreaWB_mm2: 3; SizeX_mm: 1; SizeZ_mm: 0.6; AEC Category: Q200
signal-integrity model Cap
simulation model Cap
footprint 0402
footprint 0402M
footprint 0402L
footprint 0402S
pins: 1, 2

## GRM1555C1H301GA01D
designator C?  ValueDisplayed: 300pF  (hidden comment: GRM1555C1H301GA01D)
CAP, CERM, 300 pF, 50 V,+/- 2%, C0G/NP0, 0402; Manufacturer: MuRata; Polarized: N; CompType: Capacitor; Value: 300pF; U/M: EA; Cap_F: 0.0000000003; Tolerance_%: 2; VDC_V: 50; Value2: 50V; TaMin_C: -55; TaMax_C: 125; Cap_Case: 0402; SizeArea_mm2: 0.5; SizeAreaWB_mm2: 3; SizeX_mm: 1; SizeZ_mm: 0.6; AEC Category: Q200
signal-integrity model Cap
simulation model Cap
footprint 0402
footprint 0402M
footprint 0402L
footprint 0402S
pins: 1, 2

## GRM1555C1H301JA01D
designator C?  ValueDisplayed: 300pF  (hidden comment: GRM1555C1H301JA01D)
CAP, CERM, 300 pF, 50 V,+/- 5%, C0G/NP0, 0402; Manufacturer: MuRata; Polarized: N; CompType: Capacitor; Value: 300pF; U/M: EA; Cap_F: 0.0000000003; Tolerance_%: 5; VDC_V: 50; Value2: 50V; TaMin_C: -55; TaMax_C: 125; Cap_Case: 0402; SizeArea_mm2: 0.5; SizeAreaWB_mm2: 3; SizeX_mm: 1; SizeZ_mm: 0.6; AEC Category: Q200
signal-integrity model Cap
simulation model Cap
footprint 0402
footprint 0402M
footprint 0402L
footprint 0402S
pins: 1, 2

## GRM1555C1H330JA01D
designator C?  ValueDisplayed: 33pF  (hidden comment: GRM1555C1H330JA01D)
CAP, CERM, 33 pF, 50 V,+/- 5%, C0G/NP0, 0402; Manufacturer: MuRata; Polarized: N; CompType: Capacitor; Value: 33pF; U/M: EA; Cap_F: 0.000000000033; Tolerance_%: 5; VDC_V: 50; Value2: 50V; TaMin_C: -55; TaMax_C: 125; Cap_Case: 0402; SizeArea_mm2: 0.5; SizeAreaWB_mm2: 3; SizeX_mm: 1; SizeZ_mm: 0.6; AEC Category: Q200; Green_Lifecycle: Active; Green_REACh: Passed
signal-integrity model Cap
simulation model Cap
footprint 0402
footprint 0402M
footprint 0402L
footprint 0402S
pins: 1, 2

## GRM1555C1H331FA01J
designator C?  ValueDisplayed: 330pF  (hidden comment: GRM1555C1H331FA01J)
CAP, CERM, 330 pF, 50 V,+/- 1%, C0G/NP0, 0402; Manufacturer: MuRata; Polarized: N; CompType: Capacitor; Value: 330pF; U/M: EA; Cap_F: 0.00000000033; Tolerance_%: 1; VDC_V: 50; Value2: 50V; TaMin_C: -55; TaMax_C: 125; Cap_Case: 0402; SizeArea_mm2: 0.5; SizeAreaWB_mm2: 3; SizeZ_mm: 0.6; AEC Category: Q200
signal-integrity model Cap
simulation model Cap
footprint 0402
footprint 0402M
footprint 0402L
footprint 0402S
pins: 1, 2

## GRM1555C1H331JA01D
designator C?  ValueDisplayed: 330pF  (hidden comment: GRM1555C1H331JA01D)
CAP, CERM, 330 pF, 50 V,+/- 5%, C0G/NP0, 0402; Manufacturer: MuRata; Polarized: N; CompType: Capacitor; Value: 330pF; U/M: EA; Cap_F: 0.00000000033; Tolerance_%: 5; VDC_V: 50; Value2: 50V; TaMin_C: -55; TaMax_C: 125; Cap_Case: 0402; SizeArea_mm2: 0.5; SizeAreaWB_mm2: 3; SizeX_mm: 1; SizeZ_mm: 0.6; AEC Category: Q200; Green_Lifecycle: Active; Green_REACh: Passed
signal-integrity model Cap
simulation model Cap
footprint 0402
footprint 0402M
footprint 0402L
footprint 0402S
pins: 1, 2

## GRM1555C1H361JA01D
designator C?  ValueDisplayed: 360pF  (hidden comment: GRM1555C1H361JA01D)
CAP, CERM, 360 pF, 50 V,+/- 5%, C0G/NP0, 0402; Manufacturer: MuRata; Polarized: N; CompType: Capacitor; Value: 360pF; U/M: EA; Cap_F: 0.00000000036; Tolerance_%: 5; VDC_V: 50; Value2: 50V; TaMin_C: -55; TaMax_C: 125; Cap_Case: 0402; SizeArea_mm2: 0.5; SizeAreaWB_mm2: 3; SizeX_mm: 1; SizeZ_mm: 0.6; AEC Category: Q200
signal-integrity model Cap
simulation model Cap
footprint 0402
footprint 0402M
footprint 0402L
footprint 0402S
pins: 1, 2

## GRM1555C1H390JA01D
designator C?  ValueDisplayed: 39pF  (hidden comment: GRM1555C1H390JA01D)
CAP, CERM, 39 pF, 50 V,+/- 5%, C0G/NP0, 0402; Manufacturer: MuRata; Polarized: N; CompType: Capacitor; Value: 39pF; U/M: EA; Cap_F: 0.000000000039; Tolerance_%: 5; VDC_V: 50; Value2: 50V; TaMin_C: -55; TaMax_C: 125; Cap_Case: 0402; SizeArea_mm2: 0.5; SizeAreaWB_mm2: 3; SizeX_mm: 1; SizeZ_mm: 0.6; AEC Category: Q200; Green_Lifecycle: Active; Green_REACh: Passed
signal-integrity model Cap
simulation model Cap
footprint 0402
footprint 0402M
footprint 0402L
footprint 0402S
pins: 1, 2

## GRM1555C1H391JA01D
designator C?  ValueDisplayed: 390pF  (hidden comment: GRM1555C1H391JA01D)
CAP, CERM, 390 pF, 50 V,+/- 5%, C0G/NP0, 0402; Manufacturer: MuRata; Polarized: N; CompType: Capacitor; Value: 390pF; U/M: EA; Cap_F: 0.00000000039; Tolerance_%: 5; VDC_V: 50; Value2: 50V; TaMin_C: -55; TaMax_C: 125; Cap_Case: 0402; SizeArea_mm2: 0.5; SizeAreaWB_mm2: 3; SizeX_mm: 1; SizeZ_mm: 0.6; AEC Category: Q200
signal-integrity model Cap
simulation model Cap
footprint 0402
footprint 0402M
footprint 0402L
footprint 0402S
pins: 1, 2

## GRM1555C1H430JA01D
designator C?  ValueDisplayed: 43pF  (hidden comment: GRM1555C1H430JA01D)
CAP, CERM, 43 pF, 50 V,+/- 5%, C0G/NP0, 0402; Manufacturer: MuRata; Polarized: N; CompType: Capacitor; Value: 43pF; U/M: EA; Cap_F: 0.000000000043; Tolerance_%: 5; VDC_V: 50; Value2: 50V; TaMin_C: -55; TaMax_C: 125; Cap_Case: 0402; SizeArea_mm2: 0.5; SizeAreaWB_mm2: 3; SizeX_mm: 1; SizeZ_mm: 0.6; AEC Category: Q200
signal-integrity model Cap
simulation model Cap
footprint 0402
footprint 0402M
footprint 0402L
footprint 0402S
pins: 1, 2

## GRM1555C1H431JA01D
designator C?  ValueDisplayed: 430pF  (hidden comment: GRM1555C1H431JA01D)
CAP, CERM, 430 pF, 50 V,+/- 5%, C0G/NP0, 0402; Manufacturer: MuRata; Polarized: N; CompType: Capacitor; Value: 430pF; U/M: EA; Cap_F: 0.00000000043; Tolerance_%: 5; VDC_V: 50; Value2: 50V; TaMin_C: -55; TaMax_C: 125; Cap_Case: 0402; SizeArea_mm2: 0.5; SizeAreaWB_mm2: 3; SizeX_mm: 1; SizeZ_mm: 0.6; AEC Category: Q200
signal-integrity model Cap
simulation model Cap
footprint 0402
footprint 0402M
footprint 0402L
footprint 0402S
pins: 1, 2

## GRM1555C1H470FA01D
designator C?  ValueDisplayed: 47pF  (hidden comment: GRM1555C1H470FA01D)
CAP, CERM, 47 pF, 50 V,+/- 1%, C0G/NP0, 0402; Manufacturer: MuRata; Polarized: N; CompType: Capacitor; Value: 47pF; U/M: EA; Cap_F: 0.000000000047; Tolerance_%: 1; VDC_V: 50; Value2: 50V; TaMin_C: -55; TaMax_C: 125; Cap_Case: 0402; SizeArea_mm2: 0.5; SizeAreaWB_mm2: 3; SizeZ_mm: 0.6; AEC Category: Q200; Green_Lifecycle: Active; Green_REACh: Passed
signal-integrity model Cap
simulation model Cap
footprint 0402
footprint 0402M
footprint 0402L
footprint 0402S
pins: 1, 2

## GRM1555C1H470JA01D
designator C?  ValueDisplayed: 47pF  (hidden comment: GRM1555C1H470JA01D)
CAP, CERM, 47 pF, 50 V,+/- 5%, C0G/NP0, 0402; Manufacturer: MuRata; Polarized: N; CompType: Capacitor; Value: 47pF; U/M: EA; Cap_F: 0.000000000047; Tolerance_%: 5; VDC_V: 50; Value2: 50V; TaMin_C: -55; TaMax_C: 125; Cap_Case: 0402; SizeArea_mm2: 0.5; SizeAreaWB_mm2: 3; SizeX_mm: 1; SizeZ_mm: 0.6; AEC Category: Q200; Green_Lifecycle: Active; Green_REACh: Passed
signal-integrity model Cap
simulation model Cap
footprint 0402
footprint 0402M
footprint 0402L
footprint 0402S
pins: 1, 2

## GRM1555C1H470JZ01
designator C?  ValueDisplayed: 47pF  (hidden comment: GRM1555C1H470JZ01)
CAP, CERM, 47 pF, 50 V,+/- 5%, C0G/NP0, 0402; Manufacturer: MuRata; Polarized: N; CompType: Capacitor; Value: 47pF; U/M: EA; Cap_F: 0.000000000047; Tolerance_%: 5; ESR_ohm: 0.045; Value1: 0.045 ohm; VDC_V: 50; Value2: 50V; TaMin_C: -55; TaMax_C: 125; Cap_Case: 0402; SizeArea_mm2: 0.5; SizeAreaWB_mm2: 3; SizeX_mm: 1; SizeZ_mm: 0.6; AEC Category: Q200; Green_Lifecycle: Not Set; Green_REACh: Incomplete
signal-integrity model Cap
simulation model Cap
footprint 0402
footprint 0402M
footprint 0402L
footprint 0402S
pins: 1, 2

## GRM1555C1H471JA01D
designator C?  ValueDisplayed: 470pF  (hidden comment: GRM1555C1H471JA01D)
CAP, CERM, 470 pF, 50 V,+/- 5%, C0G/NP0, 0402; Manufacturer: MuRata; Polarized: N; CompType: Capacitor; Value: 470pF; U/M: EA; Cap_F: 0.00000000047; Tolerance_%: 5; VDC_V: 50; Value2: 50V; TaMin_C: -55; TaMax_C: 125; Cap_Case: 0402; SizeArea_mm2: 0.5; SizeAreaWB_mm2: 3; SizeX_mm: 1; SizeZ_mm: 0.6; AEC Category: Q200; Green_Lifecycle: Active; Green_REACh: Passed
signal-integrity model Cap
simulation model Cap
footprint 0402
footprint 0402M
footprint 0402L
footprint 0402S
pins: 1, 2

## GRM1555C1H510GA01D
designator C?  ValueDisplayed: 51pF  (hidden comment: GRM1555C1H510GA01D)
CAP, CERM, 51 pF, 50 V,+/- 2%, C0G/NP0, 0402; Manufacturer: MuRata; Polarized: N; CompType: Capacitor; Value: 51pF; U/M: EA; Cap_F: 0.000000000051; Tolerance_%: 2; VDC_V: 50; Value2: 50V; TaMin_C: -55; TaMax_C: 125; Cap_Case: 0402; SizeArea_mm2: 0.5; SizeAreaWB_mm2: 3; SizeX_mm: 1; SizeZ_mm: 0.6; AEC Category: Q200
signal-integrity model Cap
simulation model Cap
footprint 0402
footprint 0402M
footprint 0402L
footprint 0402S
pins: 1, 2

## GRM1555C1H510JA01D
designator C?  ValueDisplayed: 51pF  (hidden comment: GRM1555C1H510JA01D)
CAP, CERM, 51 pF, 50 V,+/- 5%, C0G/NP0, 0402; Manufacturer: MuRata; Polarized: N; CompType: Capacitor; Value: 51pF; U/M: EA; Cap_F: 0.000000000051; Tolerance_%: 5; VDC_V: 50; Value2: 50V; TaMin_C: -55; TaMax_C: 125; Cap_Case: 0402; SizeArea_mm2: 0.5; SizeAreaWB_mm2: 3; SizeX_mm: 1; SizeZ_mm: 0.6; AEC Category: Q200
signal-integrity model Cap
simulation model Cap
footprint 0402
footprint 0402M
footprint 0402L
footprint 0402S
pins: 1, 2

## GRM1555C1H511GA01D
designator C?  ValueDisplayed: 510pF  (hidden comment: GRM1555C1H511GA01D)
CAP, CERM, 510 pF, 50 V,+/- 2%, C0G/NP0, 0402; Manufacturer: MuRata; Polarized: N; CompType: Capacitor; Value: 510pF; U/M: EA; Cap_F: 0.00000000051; Tolerance_%: 2; VDC_V: 50; Value2: 50V; TaMin_C: -55; TaMax_C: 125; Cap_Case: 0402; SizeArea_mm2: 0.5; SizeAreaWB_mm2: 3; SizeX_mm: 1; SizeZ_mm: 0.6; AEC Category: Q200
signal-integrity model Cap
simulation model Cap
footprint 0402
footprint 0402M
footprint 0402L
footprint 0402S
pins: 1, 2

## GRM1555C1H511JA01D
designator C?  ValueDisplayed: 510pF  (hidden comment: GRM1555C1H511JA01D)
CAP, CERM, 510 pF, 50 V,+/- 5%, C0G/NP0, 0402; Manufacturer: MuRata; Polarized: N; CompType: Capacitor; Value: 510pF; U/M: EA; Cap_F: 0.00000000051; Tolerance_%: 5; VDC_V: 50; Value2: 50V; TaMin_C: -55; TaMax_C: 125; Cap_Case: 0402; SizeArea_mm2: 0.5; SizeAreaWB_mm2: 3; SizeX_mm: 1; SizeZ_mm: 0.6; AEC Category: Q200; Green_Lifecycle: Active; Green_REACh: Passed
signal-integrity model Cap
simulation model Cap
footprint 0402
footprint 0402M
footprint 0402L
footprint 0402S
pins: 1, 2

## GRM1555C1H560JA01D
designator C?  ValueDisplayed: 56pF  (hidden comment: GRM1555C1H560JA01D)
CAP, CERM, 56 pF, 50 V,+/- 5%, C0G/NP0, 0402; Manufacturer: MuRata; Polarized: N; CompType: Capacitor; Value: 56pF; U/M: EA; Cap_F: 0.000000000056; Tolerance_%: 5; VDC_V: 50; Value2: 50V; TaMin_C: -55; TaMax_C: 125; Cap_Case: 0402; SizeArea_mm2: 0.5; SizeAreaWB_mm2: 3; SizeX_mm: 1; SizeZ_mm: 0.6; AEC Category: Q200; Green_Lifecycle: Active; Green_REACh: Passed
signal-integrity model Cap
simulation model Cap
footprint 0402
footprint 0402M
footprint 0402L
footprint 0402S
pins: 1, 2

## GRM1555C1H561JA01D
designator C?  ValueDisplayed: 560pF  (hidden comment: GRM1555C1H561JA01D)
CAP, CERM, 560 pF, 50 V,+/- 5%, C0G/NP0, 0402; Manufacturer: MuRata; Polarized: N; CompType: Capacitor; Value: 560pF; U/M: EA; Cap_F: 0.00000000056; Tolerance_%: 5; VDC_V: 50; Value2: 50V; TaMin_C: -55; TaMax_C: 125; Cap_Case: 0402; SizeArea_mm2: 0.5; SizeAreaWB_mm2: 3; SizeX_mm: 1; SizeZ_mm: 0.6; AEC Category: Q200; Green_Lifecycle: Active; Green_REACh: Passed
signal-integrity model Cap
simulation model Cap
footprint 0402
footprint 0402M
footprint 0402L
footprint 0402S
pins: 1, 2

## GRM1555C1H620JA01D
designator C?  ValueDisplayed: 62pF  (hidden comment: GRM1555C1H620JA01D)
CAP, CERM, 62 pF, 50 V,+/- 5%, C0G/NP0, 0402; Manufacturer: MuRata; Polarized: N; CompType: Capacitor; Value: 62pF; U/M: EA; Cap_F: 0.000000000062; Tolerance_%: 5; VDC_V: 50; Value2: 50V; TaMin_C: -55; TaMax_C: 125; Cap_Case: 0402; SizeArea_mm2: 0.5; SizeAreaWB_mm2: 3; SizeX_mm: 1; SizeZ_mm: 0.6; AEC Category: Q200
signal-integrity model Cap
simulation model Cap
footprint 0402
footprint 0402M
footprint 0402L
footprint 0402S
pins: 1, 2

## GRM1555C1H621JA01D
designator C?  ValueDisplayed: 620pF  (hidden comment: GRM1555C1H621JA01D)
CAP, CERM, 620 pF, 50 V,+/- 5%, C0G/NP0, 0402; Manufacturer: MuRata; Polarized: N; CompType: Capacitor; Value: 620pF; U/M: EA; Cap_F: 0.00000000062; Tolerance_%: 5; VDC_V: 50; Value2: 50V; TaMin_C: -55; TaMax_C: 125; Cap_Case: 0402; SizeArea_mm2: 0.5; SizeAreaWB_mm2: 3; SizeX_mm: 1; SizeZ_mm: 0.6; AEC Category: Q200
signal-integrity model Cap
simulation model Cap
footprint 0402
footprint 0402M
footprint 0402L
footprint 0402S
pins: 1, 2

## GRM1555C1H680JA01D
designator C?  ValueDisplayed: 68pF  (hidden comment: GRM1555C1H680JA01D)
CAP, CERM, 68 pF, 50 V,+/- 5%, C0G/NP0, 0402; Manufacturer: MuRata; Polarized: N; CompType: Capacitor; Value: 68pF; U/M: EA; Cap_F: 0.000000000068; Tolerance_%: 5; VDC_V: 50; Value2: 50V; TaMin_C: -55; TaMax_C: 125; Cap_Case: 0402; SizeArea_mm2: 0.5; SizeAreaWB_mm2: 3; SizeX_mm: 1; SizeZ_mm: 0.6; AEC Category: Q200; Green_Lifecycle: Active; Green_REACh: Passed
signal-integrity model Cap
simulation model Cap
footprint 0402
footprint 0402M
footprint 0402L
footprint 0402S
pins: 1, 2

## GRM1555C1H681JA01D
designator C?  ValueDisplayed: 680pF  (hidden comment: GRM1555C1H681JA01D)
CAP, CERM, 680 pF, 50 V,+/- 5%, C0G/NP0, 0402; Manufacturer: MuRata; Polarized: N; CompType: Capacitor; Value: 680pF; U/M: EA; Cap_F: 0.00000000068; Tolerance_%: 5; VDC_V: 50; Value2: 50V; TaMin_C: -55; TaMax_C: 125; Cap_Case: 0402; SizeArea_mm2: 0.5; SizeAreaWB_mm2: 3; SizeX_mm: 1; SizeZ_mm: 0.6; AEC Category: Q200
signal-integrity model Cap
simulation model Cap
footprint 0402
footprint 0402M
footprint 0402L
footprint 0402S
pins: 1, 2

## GRM1555C1H750JA01D
designator C?  ValueDisplayed: 75pF  (hidden comment: GRM1555C1H750JA01D)
CAP, CERM, 75 pF, 50 V,+/- 5%, C0G/NP0, 0402; Manufacturer: MuRata; Polarized: N; CompType: Capacitor; Value: 75pF; U/M: EA; Cap_F: 0.000000000075; Tolerance_%: 5; VDC_V: 50; Value2: 50V; TaMin_C: -55; TaMax_C: 125; Cap_Case: 0402; SizeArea_mm2: 0.5; SizeAreaWB_mm2: 3; SizeX_mm: 1; SizeZ_mm: 0.6; AEC Category: Q200
signal-integrity model Cap
simulation model Cap
footprint 0402
footprint 0402M
footprint 0402L
footprint 0402S
pins: 1, 2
